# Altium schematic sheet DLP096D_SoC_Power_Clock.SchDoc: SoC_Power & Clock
size 431 x 279 mm; Date: Not shown in title block; ApprovedBy: Not shown in title block; CheckedBy: Not shown in title block; Author: Not shown in title block; CompanyName: Not shown in title block; Engineer: Not shown in title block; Organization: Not shown in title block; Address1: Not shown in title block; Address2: Not shown in title block; Address3: Not shown in title block; Address4: Not shown in title block; DocumentNumber: 4; Revision: Use project parameter SCH_Rev; SheetNumber: 4; SheetTotal: 10; PageSetup: Record=PageOptions¦CenterHorizontal=True¦CenterVertical=True¦PrintScale=1.00¦XCorrection=1.00¦YCorrection=1.00¦PrintKind=0¦BorderSize=5000000¦LeftOffset=0¦BottomOffset=0¦Orientation=2¦PaperLength=1000¦PaperWidth=1000¦Scale=100¦PaperSource=15¦PrintQuality=600¦MediaType=1¦DitherType=10¦PaperKind=Letter¦PrintScaleMode=1
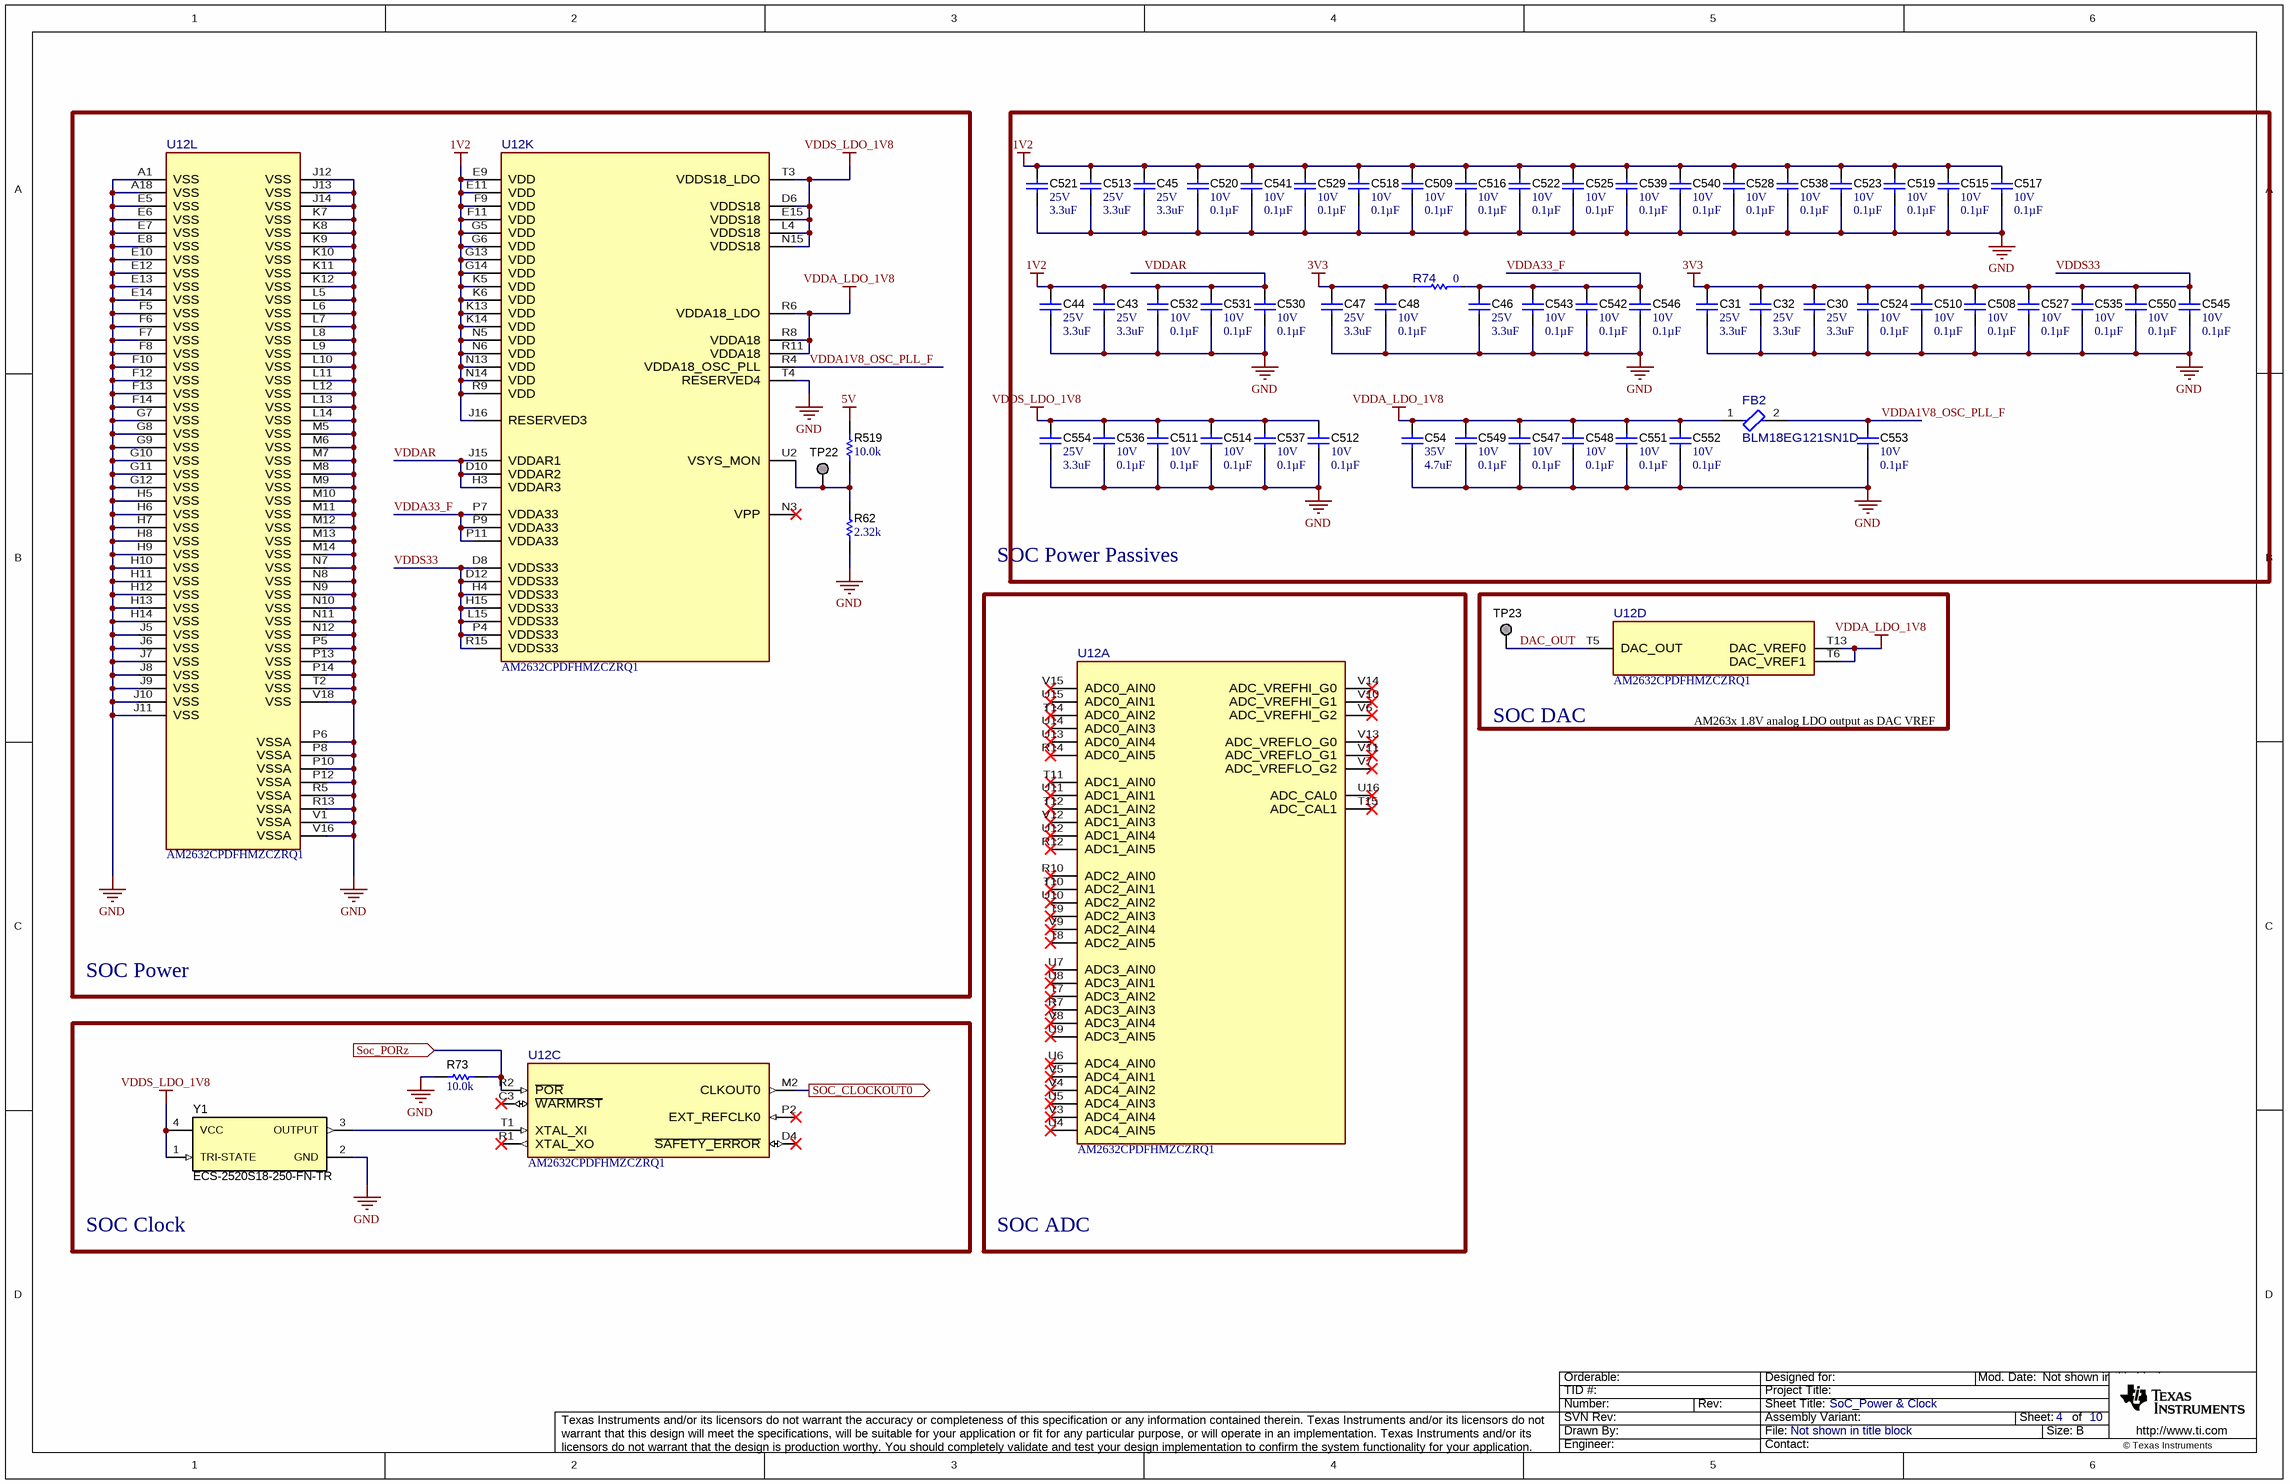
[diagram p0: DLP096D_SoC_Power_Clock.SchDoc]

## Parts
C30  VDC_V: 25V  ValueDisplayed: 3.3uF  [0603]  (hidden comment: C1608X5R1E335K080AC)
C31  VDC_V: 25V  ValueDisplayed: 3.3uF  [0603]  (hidden comment: C1608X5R1E335K080AC)
C32  VDC_V: 25V  ValueDisplayed: 3.3uF  [0603]  (hidden comment: C1608X5R1E335K080AC)
C43  VDC_V: 25V  ValueDisplayed: 3.3uF  [0603]  (hidden comment: C1608X5R1E335K080AC)
C44  VDC_V: 25V  ValueDisplayed: 3.3uF  [0603]  (hidden comment: C1608X5R1E335K080AC)
C45  VDC_V: 25V  ValueDisplayed: 3.3uF  [0603]  (hidden comment: C1608X5R1E335K080AC)
C46  VDC_V: 25V  ValueDisplayed: 3.3uF  [0603]  (hidden comment: C1608X5R1E335K080AC)
C47  VDC_V: 25V  ValueDisplayed: 3.3uF  [0603]  (hidden comment: C1608X5R1E335K080AC)
C48  VDC_V: 10V  ValueDisplayed: 0.1µF  [0201_033]  (hidden comment: GRM033R61A104KE84D)
C54  VDC_V: 35V  ValueDisplayed: 4.7uF  [0603]  (hidden comment: C1608X5R1V475K080AC)
C508  VDC_V: 10V  ValueDisplayed: 0.1µF  [0201_033]  (hidden comment: GRM033R61A104KE84D)
C509  VDC_V: 10V  ValueDisplayed: 0.1µF  [0201_033]  (hidden comment: GRM033R61A104KE84D)
C510  VDC_V: 10V  ValueDisplayed: 0.1µF  [0201_033]  (hidden comment: GRM033R61A104KE84D)
C511  VDC_V: 10V  ValueDisplayed: 0.1µF  [0201_033]  (hidden comment: GRM033R61A104KE84D)
C512  VDC_V: 10V  ValueDisplayed: 0.1µF  [0201_033]  (hidden comment: GRM033R61A104KE84D)
C513  VDC_V: 25V  ValueDisplayed: 3.3uF  [0603]  (hidden comment: C1608X5R1E335K080AC)
C514  VDC_V: 10V  ValueDisplayed: 0.1µF  [0201_033]  (hidden comment: GRM033R61A104KE84D)
C515  VDC_V: 10V  ValueDisplayed: 0.1µF  [0201_033]  (hidden comment: GRM033R61A104KE84D)
C516  VDC_V: 10V  ValueDisplayed: 0.1µF  [0201_033]  (hidden comment: GRM033R61A104KE84D)
C517  VDC_V: 10V  ValueDisplayed: 0.1µF  [0201_033]  (hidden comment: GRM033R61A104KE84D)
C518  VDC_V: 10V  ValueDisplayed: 0.1µF  [0201_033]  (hidden comment: GRM033R61A104KE84D)
C519  VDC_V: 10V  ValueDisplayed: 0.1µF  [0201_033]  (hidden comment: GRM033R61A104KE84D)
C520  VDC_V: 10V  ValueDisplayed: 0.1µF  [0201_033]  (hidden comment: GRM033R61A104KE84D)
C521  VDC_V: 25V  ValueDisplayed: 3.3uF  [0603]  (hidden comment: C1608X5R1E335K080AC)
C522  VDC_V: 10V  ValueDisplayed: 0.1µF  [0201_033]  (hidden comment: GRM033R61A104KE84D)
C523  VDC_V: 10V  ValueDisplayed: 0.1µF  [0201_033]  (hidden comment: GRM033R61A104KE84D)
C524  VDC_V: 10V  ValueDisplayed: 0.1µF  [0201_033]  (hidden comment: GRM033R61A104KE84D)
C525  VDC_V: 10V  ValueDisplayed: 0.1µF  [0201_033]  (hidden comment: GRM033R61A104KE84D)
C527  VDC_V: 10V  ValueDisplayed: 0.1µF  [0201_033]  (hidden comment: GRM033R61A104KE84D)
C528  VDC_V: 10V  ValueDisplayed: 0.1µF  [0201_033]  (hidden comment: GRM033R61A104KE84D)
C529  VDC_V: 10V  ValueDisplayed: 0.1µF  [0201_033]  (hidden comment: GRM033R61A104KE84D)
C530  VDC_V: 10V  ValueDisplayed: 0.1µF  [0201_033]  (hidden comment: GRM033R61A104KE84D)
C531  VDC_V: 10V  ValueDisplayed: 0.1µF  [0201_033]  (hidden comment: GRM033R61A104KE84D)
C532  VDC_V: 10V  ValueDisplayed: 0.1µF  [0201_033]  (hidden comment: GRM033R61A104KE84D)
C535  VDC_V: 10V  ValueDisplayed: 0.1µF  [0201_033]  (hidden comment: GRM033R61A104KE84D)
C536  VDC_V: 10V  ValueDisplayed: 0.1µF  [0201_033]  (hidden comment: GRM033R61A104KE84D)
C537  VDC_V: 10V  ValueDisplayed: 0.1µF  [0201_033]  (hidden comment: GRM033R61A104KE84D)
C538  VDC_V: 10V  ValueDisplayed: 0.1µF  [0201_033]  (hidden comment: GRM033R61A104KE84D)
C539  VDC_V: 10V  ValueDisplayed: 0.1µF  [0201_033]  (hidden comment: GRM033R61A104KE84D)
C540  VDC_V: 10V  ValueDisplayed: 0.1µF  [0201_033]  (hidden comment: GRM033R61A104KE84D)
C541  VDC_V: 10V  ValueDisplayed: 0.1µF  [0201_033]  (hidden comment: GRM033R61A104KE84D)
C542  VDC_V: 10V  ValueDisplayed: 0.1µF  [0201_033]  (hidden comment: GRM033R61A104KE84D)
C543  VDC_V: 10V  ValueDisplayed: 0.1µF  [0201_033]  (hidden comment: GRM033R61A104KE84D)
C545  VDC_V: 10V  ValueDisplayed: 0.1µF  [0201_033]  (hidden comment: GRM033R61A104KE84D)
C546  VDC_V: 10V  ValueDisplayed: 0.1µF  [0201_033]  (hidden comment: GRM033R61A104KE84D)
C547  VDC_V: 10V  ValueDisplayed: 0.1µF  [0201_033]  (hidden comment: GRM033R61A104KE84D)
C548  VDC_V: 10V  ValueDisplayed: 0.1µF  [0201_033]  (hidden comment: GRM033R61A104KE84D)
C549  VDC_V: 10V  ValueDisplayed: 0.1µF  [0201_033]  (hidden comment: GRM033R61A104KE84D)
C550  VDC_V: 10V  ValueDisplayed: 0.1µF  [0201_033]  (hidden comment: GRM033R61A104KE84D)
C551  VDC_V: 10V  ValueDisplayed: 0.1µF  [0201_033]  (hidden comment: GRM033R61A104KE84D)
C552  VDC_V: 10V  ValueDisplayed: 0.1µF  [0201_033]  (hidden comment: GRM033R61A104KE84D)
C553  VDC_V: 10V  ValueDisplayed: 0.1µF  [0201_033]  (hidden comment: GRM033R61A104KE84D)
C554  VDC_V: 25V  ValueDisplayed: 3.3uF  [0603]  (hidden comment: C1608X5R1E335K080AC)
FB2  BLM18EG121SN1D  [FP-BLM18EG121SN1D_0603-MFG]
R62  ValueDisplayed: 2.32k  [0402]  (hidden comment: CRCW04022K32FKED)
R73  ValueDisplayed: 10.0k  [0402]  (hidden comment: CRCW040210K0FKED)
R74  Res_ohm: 0  [FP-RMCF0805ZT0R00_0805-IPC_C]  (hidden comment: RMCF0805ZT0R00)
R519  ValueDisplayed: 10.0k  [0402]  (hidden comment: CRCW040210K0FKED)
TP22  TP_H0.45P0.75  [TP_H045P075]  (value not drawn)  (no BOM)
TP23  DAC_OUT  [TP_H045P075]  (value not drawn)  (no BOM)
U12  PartNumber: AM2632CPDFHMZCZRQ1  [ZCZ0324A-MFG]  (hidden comment: XAM2634AOLFGMZCZQ)  (parts A,C,D,K,L of 13)
Y1  ECS-2520S18-250-FN-TR  [ECS_ECS-2520S]

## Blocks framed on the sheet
SOC Power: R62 R519 TP22 U12
SOC ADC: U12
SOC DAC: TP23 U12
SOC Clock: R73 U12 Y1

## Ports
SOC_CLOCKOUT0 (out), Soc_PORz (in)

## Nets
5V: R519.2
GND: C30.2 C31.2 C32.2 C43.2 C44.2 C45.2 C46.2 C47.2 C48.2 C54.2 C508.2 C509.2 C510.2 C511.2 C512.2 C513.2 C514.2 C515.2 C516.2 C517.2 C518.2 C519.2 C520.2 C521.2 C522.2 C523.2 C524.2 C525.2 C527.2 C528.2 C529.2 C530.2 C531.2 C532.2 C535.2 C536.2 C537.2 C538.2 C539.2 C540.2 C541.2 C542.2 C543.2 C545.2 C546.2 C547.2 C548.2 C549.2 C550.2 C551.2 C552.2 C553.2 C554.2 R62.1 R73.2 U12.A1(VSS) U12.A18(VSS) U12.E5(VSS) U12.E6(VSS) U12.E7(VSS) U12.E8(VSS) U12.E10(VSS) U12.E12(VSS) U12.E13(VSS) U12.E14(VSS) U12.F5(VSS) U12.F6(VSS) U12.F7(VSS) U12.F8(VSS) U12.F10(VSS) U12.F12(VSS) U12.F13(VSS) U12.F14(VSS) U12.G7(VSS) U12.G8(VSS) U12.G9(VSS) U12.G10(VSS) U12.G11(VSS) U12.G12(VSS) U12.H5(VSS) U12.H6(VSS) U12.H7(VSS) U12.H8(VSS) U12.H9(VSS) U12.H10(VSS) U12.H11(VSS) U12.H12(VSS) U12.H13(VSS) U12.H14(VSS) U12.J5(VSS) U12.J6(VSS) U12.J7(VSS) U12.J8(VSS) U12.J9(VSS) U12.J10(VSS) U12.J11(VSS) U12.J12(VSS) U12.J13(VSS) U12.J14(VSS) U12.K7(VSS) U12.K8(VSS) U12.K9(VSS) U12.K10(VSS) U12.K11(VSS) U12.K12(VSS) U12.L5(VSS) U12.L6(VSS) U12.L7(VSS) U12.L8(VSS) U12.L9(VSS) U12.L10(VSS) U12.L11(VSS) U12.L12(VSS) U12.L13(VSS) U12.L14(VSS) U12.M5(VSS) U12.M6(VSS) U12.M7(VSS) U12.M8(VSS) U12.M9(VSS) U12.M10(VSS) U12.M11(VSS) U12.M12(VSS) U12.M13(VSS) U12.M14(VSS) U12.N7(VSS) U12.N8(VSS) U12.N9(VSS) U12.N10(VSS) U12.N11(VSS) U12.N12(VSS) U12.P5(VSS) U12.P6(VSSA) U12.P8(VSSA) U12.P10(VSSA) U12.P12(VSSA) U12.P13(VSS) U12.P14(VSS) U12.R5(VSSA) U12.R13(VSSA) U12.T2(VSS) U12.T4(RESERVED4) U12.V1(VSSA) U12.V16(VSSA) U12.V18(VSS) Y1.2(GND)
VDDA_LDO_1V8: C54.1 C547.1 C548.1 C549.1 C551.1 C552.1 FB2.1 U12.R6(VDDA18_LDO) U12.R8(VDDA18) U12.R11(VDDA18) U12.T6(DAC_VREF1) U12.T13(DAC_VREF0)
VDDAR: C43.1 C44.1 C45.1 C509.1 C513.1 C515.1 C516.1 C517.1 C518.1 C519.1 C520.1 C521.1 C522.1 C523.1 C525.1 C528.1 C529.1 C530.1 C531.1 C532.1 C538.1 C539.1 C540.1 C541.1 U12.D10(VDDAR2) U12.E9(VDD) U12.E11(VDD) U12.F9(VDD) U12.F11(VDD) U12.G5(VDD) U12.G6(VDD) U12.G13(VDD) U12.G14(VDD) U12.H3(VDDAR3) U12.J15(VDDAR1) U12.J16(RESERVED3) U12.K5(VDD) U12.K6(VDD) U12.K13(VDD) U12.K14(VDD) U12.N5(VDD) U12.N6(VDD) U12.N13(VDD) U12.N14(VDD) U12.R9(VDD)  [also labelled 1V2]
VDDS33: C30.1 C31.1 C32.1 C47.1 C48.1 C508.1 C510.1 C524.1 C527.1 C535.1 C545.1 C550.1 R74.1 U12.D8(VDDS33) U12.D12(VDDS33) U12.H4(VDDS33) U12.H15(VDDS33) U12.L15(VDDS33) U12.P4(VDDS33) U12.R15(VDDS33)  [also labelled 3V3]
VDDS_LDO_1V8: C511.1 C512.1 C514.1 C536.1 C537.1 C554.1 U12.D6(VDDS18) U12.E15(VDDS18) U12.L4(VDDS18) U12.N15(VDDS18) U12.T3(VDDS18_LDO) Y1.1(TRI-STATE) Y1.4(VCC)
DAC_OUT: TP23.1 U12.T5(DAC_OUT)
SOC_CLOCKOUT0: U12.M2(CLKOUT0) ; port SOC_CLOCKOUT0
Soc_PORz: R73.1 U12.R2(~{POR}) ; port Soc_PORz
VDDA1V8_OSC_PLL_F: C553.1 FB2.2 U12.R4(VDDA18_OSC_PLL)
VDDA33_F: C46.1 C542.1 C543.1 C546.1 R74.2 U12.P7(VDDA33) U12.P9(VDDA33) U12.P11(VDDA33)
NetR62_2: R62.2 R519.1 TP22.1 U12.U2(VSYS_MON)
NetU12_T1: U12.T1(XTAL_XI) Y1.3(OUTPUT)

Not connected (* = marked no-connect by the designer): U12 C3(~{WARMRST})* D4(~{SAFETY_ERROR})* N3(VPP)* P2(EXT_REFCLK0)* R1(XTAL_XO)* R7(ADC3_AIN3)* R10(ADC2_AIN0)* R12(ADC1_AIN5)* R14(ADC0_AIN5)* T7(ADC3_AIN2)* T8(ADC2_AIN5)* T9(ADC2_AIN3)* T10(ADC2_AIN1)* T11(ADC1_AIN0)* T12(ADC1_AIN2)* T14(ADC0_AIN2)* T15(ADC_CAL1)* U4(ADC4_AIN5)* U5(ADC4_AIN3)* U6(ADC4_AIN0)* U7(ADC3_AIN0)* U8(ADC3_AIN1)* U9(ADC3_AIN5)* U10(ADC2_AIN2)* U11(ADC1_AIN1)* U12(ADC1_AIN4)* U13(ADC0_AIN4)* U14(ADC0_AIN3)* U15(ADC0_AIN1)* U16(ADC_CAL0)* V3(ADC4_AIN4)* V4(ADC4_AIN2)* V5(ADC4_AIN1)* V6(ADC_VREFHI_G2)* V7(ADC_VREFLO_G2)* V8(ADC3_AIN4)* V9(ADC2_AIN4)* V10(ADC_VREFHI_G1)* V11(ADC_VREFLO_G1)* V12(ADC1_AIN3)* V13(ADC_VREFLO_G0)* V14(ADC_VREFHI_G0)* V15(ADC0_AIN0)*

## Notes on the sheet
- SOC Power Passives
- (near U12) AM263x 1.8V analog LDO output as DAC VREF

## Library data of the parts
C30-C32 C43-C47 C513 C521 C554 = CMP-0007008-1: CAP, CERM, 3.3 uF, 25 V, +/- 10%, X5R, 0603; Manufacturer: TDK; TaMin_C: -55°C; Polarized: N; SizeAreaWB_mm2: 4.68; Value1: Unknown; U/M: EA; Value: 3.3uF; TaMax_C: 85°C; SizeZ_mm: 1; SizeX_mm: 1.6; SizeY_mm: 0.8; SizeArea_mm2: 1.28; Cap_F: 3.3µF; AEC Category: Q200
C48 C508-C512 C514-C520 C522-C525 C527-C532 C535-C543 C545-C553 = CMP-0086059-1: CAP, CERM, 0.1 µF, 10 V,+/- 10%, X5R, 0201; Manufacturer: MuRata; AEC Category: Q200; Cap_F: 100nF; Value: 0.1uF; SizeY_mm: 0.3; AEC Qualified: N; SizeAreaWB_mm2: 2.08; Cap_Case: 0201; SizeArea_mm2: 0.18; SizeZ_mm: 0.33; SizeX_mm: 0.6; TaMax_C: 85°C; TaMin_C: -55°C; U/M: EA
C54 = CMP-0007022-5: CAP, CERM, 4.7 uF, 35 V, +/- 10%, X5R, 0603; Manufacturer: TDK; TaMin_C: -55°C; ESR_ohm: 3.728m; Polarized: N; SizeAreaWB_mm2: 4.68; Value1: 0.003728 ohm; U/M: EA; Value: 4.7uF; TaMax_C: 85°C; SizeZ_mm: 1; SizeX_mm: 1.6; SizeY_mm: 0.8; SizeArea_mm2: 1.28; Cap_F: 4.7µF; IRMS_A: 2.6936A; AEC Category: Q200
FB2 = CMP-0089199-1: 120 Ohms @ 100MHz 1  Ferrite Bead 0603 (1608 Metric) 2A 40mOhm; Manufacturer: Murata; DCR_ohm: 60m; AEC Qualified: No; Tolerance_%: 25%; SizeZ_mm: 0.95mm; Impedance At Frequency: 120Ω @ 100MHz
R62 = CMP-0026240-2: RES, 2.32 k, 1%, 0.063 W, AEC-Q200 Grade 0, 0402; Manufacturer: Vishay-Dale; Power_W: 63mW; TempCo: 100 ppm/C; Value_Code: 2k32; Value: 2.32k; EIA_Code: E96; Res_ohm: 2.67k; SizeX_mm: 1; SizeY_mm: 0.5; SizeZ_mm: 0.6; Value2: 0.063W; AEC Qualified: Y; VDC_V: 50V; AEC Category: Q200; AEC Grade: 0
R73 R519 = CMP-0025958-2: RES, 10.0 k, 1%, 0.063 W, 0402; Manufacturer: Vishay-Dale; Power_W: 63mW; TempCo: 100 ppm/C; Value_Code: 10k0; U/M: EA; Value: 10.0k; EIA_Code: E96; Res_ohm: 10k; SizeX_mm: 1; SizeY_mm: 0.5; SizeZ_mm: 0.6; Value2: 0.063W; VDC_V: 50V; AEC Category: Q200
R74 = CMP-0089632-1: 0 Ohms Jumper 0.125W, 1/8W Chip Resistor 0805 (2012 Metric) Automotive AEC-Q200 Thick Film; Manufacturer: Stackpole Electronics; SizeZ_mm: 0.65mm; Power_W: 125mW; AEC Grade: Grade 0; AEC Qualified: Yes; TempCo: 200ppm/°C; VDC_V: 150V
TP22 = CMP-0003719-1: Testpoint; Manufacturer: Texas Instruments; CompType: Pad
TP23 = CMP-0003719-1: Testpoint; Manufacturer: Texas Instruments; Key: TP_H0.45P0.75; CompType: Pad
U12 = CMP-0093674-1: Sitara™ Microcontrollers; Manufacturer: Texas Instruments; Min Supply Voltage: 1.14V; Number Of Adc Channels: 30; AEC Qualified: No; TJmax_C: +105°C; Memory Type: SRAM; Standoff Height: 0.35mm; Core Architecture: ARM Cortex-R5F; Number Of I2C Channels: 4; Number Of Pwm Channels: 24; Number Of Spi Channels: 5; Number Of Cores: 2; Frequency_Fixed: 400MHz; Nominal Supply Current: 200-2500mA; Ram Size: 2MBytes; Number Of Ethernet Channels: 1; Interface: I2C,SPI,UART,CAN,LIN,Ethernet,Other; Data Bus Width: 64bits; SizeZ_mm: 1.4mm; Number Of Uart Channels: 6; Number Of I/Os: 140; Max Supply Voltage: 3.465V
Y1 = CMP-0082061-2: Oscillator, 25 MHz, 15 pF, SMD; Manufacturer: ECS Inc.; SizeAreaWB_mm2: 10.5; Frequency Stability: 10 ppm; SizeY_mm: 2.5; SizeZ_mm: 1; AEC Category: Q200; TaMax_C: 85°C; Load Capacitance: 15 pF; AEC Qualified: N; SizeX_mm: 2; TaMin_C: -40°C; Frequency_Fixed: 25MHz; SizeArea_mm2: 5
